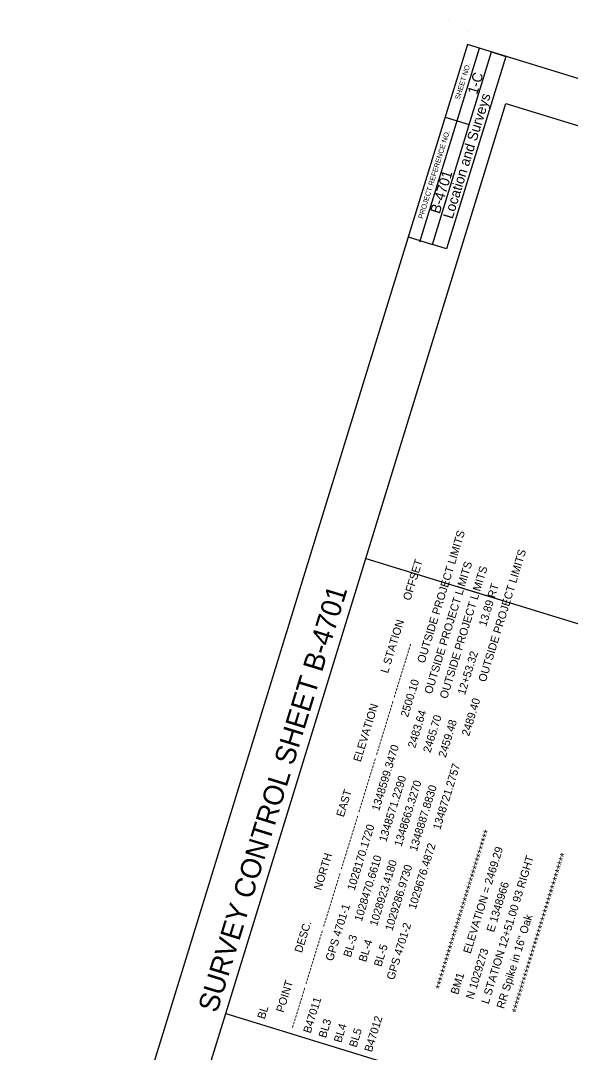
# Model space of a CAD drawing. Extents: x 1348011 to 1349268, y 1028333 to 1030014.
# Drawn here: x 1348011 to 1348484, y 1029127 to 1030014 of the extents above; entities that cross this region are included whole.
import ezdxf

# ---------------------------------------------------------------- set-up
doc = ezdxf.new("R2010")
doc.units = 0
for name, color, linetype in [('CTL Sheet Border CELL', 7, 'Continuous'), ('CTL Sheet Text', 7, 'Continuous'), ('Scratch_Level_3', 7, 'Continuous'), ('Sheet Data Field CELL', 7, 'Continuous')]:
    doc.layers.add(name, color=color, linetype=linetype)

msp = doc.modelspace()

# ---------------------------------------------------------------- linework, layer by layer
at = {"layer": 'CTL Sheet Border CELL'}
for p, q in [((1348378.73, 1030013.54), (1348378.73, 1030013.54)), ((1348396.22, 1030004.06), (1348396.22, 1030004.06)), ((1348396.22, 1030004.06), (1348396.22, 1030004.06)), ((1348354.38, 1029823.54), (1348405.58, 1029989.8)), ((1348375.99, 1029930.68), (1348396.77, 1029924.28)), ((1348344.27, 1029827.69), (1348365.05, 1029821.29))]:
    msp.add_line(p, q, dxfattribs=at)
for points in [[(1348395.15, 1029993.01), (1348011.26, 1028746.43), (1348883.85, 1028477.71), (1349267.74, 1029724.29)], [(1348365.05, 1029821.29), (1348415.96, 1029986.6), (1348428.19, 1029982.84), (1348377.28, 1029817.52)]]:
    msp.add_lwpolyline(points, close=True, dxfattribs=at)
at = {"layer": 'Scratch_Level_3'}
for p, q in [((1348307.95, 1029551.47), (1348428.33, 1029942.38)), ((1348428.33, 1029942.38), (1349072.16, 1029744.11)), ((1348187.56, 1029160.56), (1348307.95, 1029551.47)), ((1348307.95, 1029551.47), (1348951.78, 1029353.2)), ((1348067.18, 1028769.65), (1348187.56, 1029160.56)), ((1348187.56, 1029160.56), (1348831.4, 1028962.29))]:
    msp.add_line(p, q, dxfattribs=at)

# ---------------------------------------------------------------- texts
at = {"layer": 'CTL Sheet Border CELL'}
for s, height, p in [('SHEET NO.', 4.348, (1348388.46, 1029945.32)), ('Location and Surveys', 8.6958, (1348382.39, 1029842.66)), ('PROJECT REFERENCE NO.', 4.3479, (1348356.86, 1029843)), ('SURVEY CONTROL SHEET B-4701', 17.3913, (1348180, 1029160.33))]:
    msp.add_text(s, height=height, rotation=72.88342, dxfattribs=at).set_placement(p)
at = {"layer": 'CTL Sheet Text'}
for s, p in [('B47011             GPS 4701-1     1028170.1720     1348599.3470          2500.10      OUTSIDE PROJECT LIMITS                 ', (1348260.41, 1029142.97)), ('B47012             GPS 4701-2     1029676.4872     1348721.2757          2489.40      OUTSIDE PROJECT LIMITS                 ', (1348312.97, 1029126.78)), ('    POINT          DESC.           NORTH             EAST          ELEVATION           L STATION       OFFSET', (1348234.13, 1029151.07)), ('BL3                      BL-3     1028470.6610     1348571.2290          2483.64      OUTSIDE PROJECT LIMITS                 ', (1348273.55, 1029138.92)), ('BL4                      BL-4     1028923.4180     1348663.3270          2465.70      OUTSIDE PROJECT LIMITS                 ', (1348286.69, 1029134.88)), ('BL5                      BL-5     1029286.9730     1348887.8830          2459.48         12+53.32         13.89 RT', (1348299.83, 1029130.83)), ('------------ ---------------- ---------------- ---------------- ---------------- ---------------- ----------------', (1348247.27, 1029147.02)), ('****************************************', (1348373.95, 1029180.28)), ('BM1       ELEVATION = 2469.29', (1348387.09, 1029176.23)), ('L STATION 12+51.00 93 RIGHT', (1348413.38, 1029168.14)), ('****************************************', (1348439.66, 1029160.04)), ('N 1029273      E 1348966', (1348400.24, 1029172.18)), ('RR Spike in 16" Oak', (1348426.52, 1029164.09)), ('BL', (1348220.98, 1029155.11))]:
    msp.add_text(s, height=6.875, rotation=72.88342, dxfattribs=at).set_placement(p)
at = {"layer": 'Sheet Data Field CELL'}
for s, p in [('1-C', (1348403.46, 1029949.45)), ('B-4701', (1348371.33, 1029847.07))]:
    msp.add_text(s, height=8.75, rotation=72.88342, dxfattribs=at).set_placement(p)

doc.saveas('drawing.dxf')
